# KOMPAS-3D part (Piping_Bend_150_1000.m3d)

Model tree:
1. Plane XY
2. Plane ZX
3. Plane ZY
4. X Axis
5. Y Axis
6. Z Axis
7. Origin
8. Sketch:1
9. Sketch:5
10. Sweep:1
     Толщина стенки 1 = 1
11. Control point:1
12. Attachment Point:1
13. Attachment Point:2

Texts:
  Bend-90 Dn 150
  Steel ASTM A295
  Three Point Plane
  Plane at Angle
  Line and Point Plane
  Axis through Two Vertices
  Axis of Feature
  Axis of Conical Surface
  Axis through Edge
  Приклеить элемент выдавливания
  Приклеить элемент вращения
  Приклеить кинематический элемент
  Приклеить элемент по сечениям
  Trim by Surface
  Trim by Sketch
  Feature with No History
  Intersection Axis of Two Planes
  Two Line Plane
  Line and Face Plane
  Bend by line
  Hole in sheet body
  Cut in sheet body
  Point in CM
  Linear Dimension from Line to Point
  Surface Finish Symbol
  Geometric Tolerance Symbol
  Текст на чертеже
  Линия-выноска #1
  Линия-выноска #2
  Линия-выноска #3
  Отклонения формы и база
  Марка координационной оси
  Марка/позиционное обозначение с линией-выноской
  Марка/позиционное обозначение на линии
  Марка/позиционное обозначение без линии-выноски
  Марки/позиционные обозначения с линией-выноской
  Марки/позиционные обозначения на линии
  Марки/позиционные обозначения без линии-выноски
